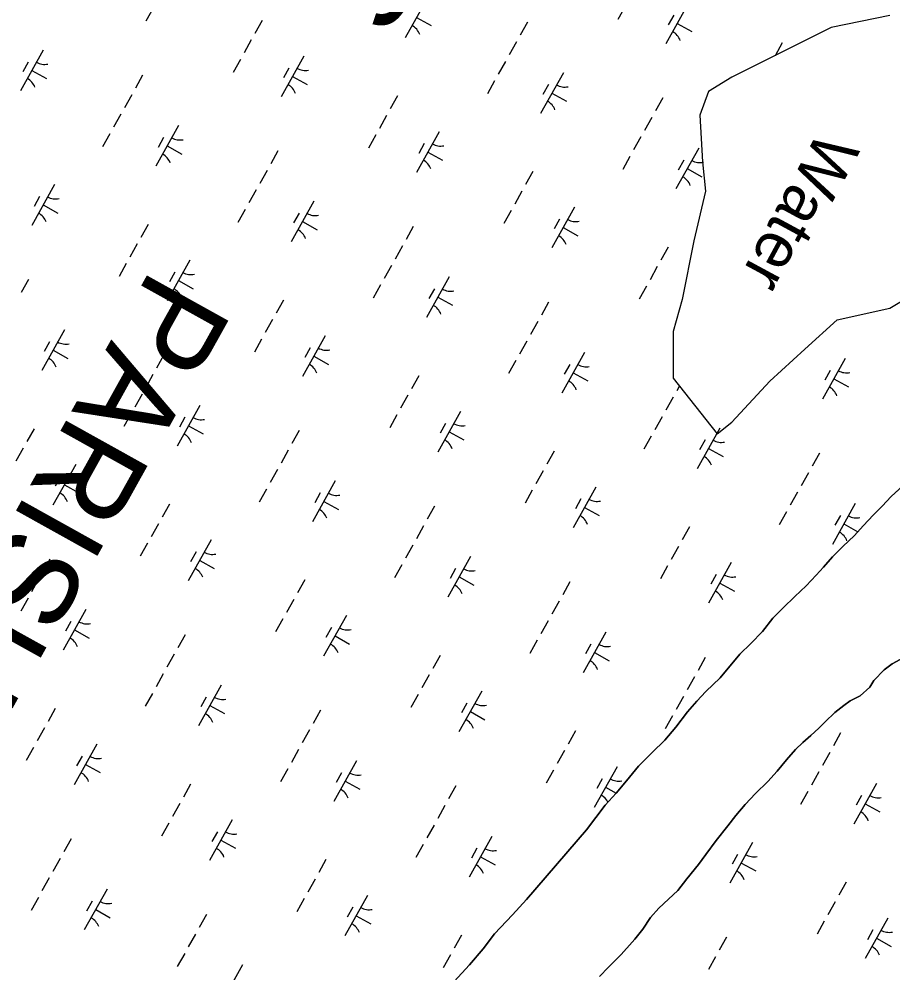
# Model space of a CAD drawing. Extents: x 3923531 to 3943530, y 207391 to 229799.
# Drawn here: x 3929310 to 3930247, y 215493 to 216516 of the extents above; entities that cross this region are included whole.
import ezdxf

# ---------------------------------------------------------------- set-up
doc = ezdxf.new("R2010")
doc.units = 0
for name, color, linetype in [('V-RIVR-IDEN', 7, 'Continuous'), ('V-TOPO-GNAM-IDEN', 7, 'Continuous'), ('V-TOPO-SHOR', 7, 'Continuous'), ('V-WETL-SWMP', 7, 'Continuous')]:
    doc.layers.add(name, color=color, linetype=linetype)

msp = doc.modelspace()

# ---------------------------------------------------------------- linework, layer by layer
at = {"layer": 'V-TOPO-SHOR'}
for points in [[(3930244, 216520.1), (3930181.2, 216507.5), (3930074.5, 216454.1), (3930049.4, 216438.5), (3930040, 216413.3), (3930043.1, 216363.1), (3930046.2, 216331.7), (3930033.7, 216278.4), (3930021.1, 216215.6), (3930011.7, 216181.1), (3930011.7, 216130.9), (3930058.8, 216071.2), (3930074.5, 216083.8), (3930115.3, 216127.7), (3930152.9, 216162.2), (3930187.5, 216193.6), (3930244, 216206.2), (3930275.4, 216225)], [(3929776.4, 215483.4), (3929793.1, 215501.4), (3929807.7, 215518.7), (3929819.9, 215534.8), (3929839.1, 215555.2), (3929854.3, 215571.6), (3929918.4, 215646.4), (3929938.7, 215672.7), (3929950.3, 215685.5), (3929961.5, 215699), (3929974.5, 215714.7), (3929989.1, 215729.4), (3930002.5, 215742.5), (3930014.3, 215756.6), (3930027, 215772.9), (3930036.8, 215784.3), (3930046.4, 215794.7), (3930062, 215809.6), (3930083.2, 215834.7), (3930095, 215846.4), (3930107.2, 215859.3), (3930118.4, 215873.3), (3930129.4, 215884.4), (3930142.2, 215896.6), (3930154.2, 215908.3), (3930165, 215919.5), (3930172.8, 215928.3), (3930182.6, 215939.3), (3930193.6, 215950.2), (3930206, 215962.2), (3930215.4, 215972.6), (3930226.4, 215984.3), (3930235.6, 215993.7), (3930245.4, 216004.1), (3930274.1, 216030.3)], [(3929932.5, 215489.1), (3929942.1, 215499.1), (3929955.7, 215512.4), (3929967.7, 215525.7), (3929970.3, 215528.9), (3929979, 215539.8), (3929987.2, 215552.2), (3929996.2, 215562.2), (3930006.6, 215572), (3930016.4, 215581.2), (3930026.2, 215593.6), (3930038.6, 215609.3), (3930046.5, 215619.7), (3930057.7, 215635), (3930070.3, 215650.7), (3930078.9, 215661.7), (3930088.8, 215673.4), (3930100, 215685.4), (3930113, 215698.1), (3930123.2, 215709.3), (3930133.2, 215721.6), (3930142.8, 215732.4), (3930150.8, 215740.2), (3930159.2, 215747.7), (3930167.9, 215755.3), (3930174.7, 215762.2), (3930184.9, 215772.1), (3930194.7, 215779.8), (3930201.3, 215784.6), (3930212.2, 215790.3), (3930222.4, 215799.3), (3930227, 215806.5), (3930237.8, 215817.9), (3930246.6, 215824.5), (3930255, 215829)]]:
    msp.add_lwpolyline(points, dxfattribs=at)
at = {"layer": 'V-WETL-SWMP'}
for p, q in [((3929470, 216557.8), (3929445.7, 216514.1)), ((3929748.5, 216540), (3929724.1, 216496.3)), ((3930028.1, 216533.5), (3930003.7, 216489.8)), ((3929960, 216529.9), (3929952.2, 216516)), ((3929570.6, 216515), (3929562.8, 216501)), ((3929736.3, 216518.1), (3929752, 216509.4)), ((3929855.1, 216512.9), (3929847.3, 216499)), ((3930012.1, 216520.7), (3930006.2, 216510.2)), ((3930015.9, 216511.7), (3930031.6, 216502.9)), ((3929558.9, 216494.1), (3929551.1, 216480.1)), ((3929843.4, 216492), (3929835.6, 216478)), ((3929335.6, 216483.1), (3929311.2, 216439.5)), ((3930128.6, 216490.7), (3930120.8, 216476.8)), ((3929547.2, 216473.1), (3929539.4, 216459.1)), ((3929615.3, 216476.7), (3929590.9, 216433)), ((3929831.7, 216471), (3929823.9, 216457.1)), ((3929319.6, 216470.3), (3929313.8, 216459.8)), ((3929323.4, 216461.3), (3929339.2, 216452.5)), ((3929599.3, 216463.8), (3929593.4, 216453.4)), ((3929442.3, 216456.1), (3929434.5, 216442.1)), ((3929603.1, 216454.8), (3929618.8, 216446)), ((3929893.7, 216458.8), (3929869.3, 216415.2)), ((3929820, 216450.1), (3929812.2, 216436.1)), ((3929877.7, 216446), (3929871.8, 216435.5)), ((3929430.6, 216435.1), (3929422.8, 216421.2)), ((3929715.8, 216433.9), (3929708, 216419.9)), ((3929881.5, 216437), (3929897.2, 216428.2)), ((3930000.3, 216431.8), (3929992.5, 216417.8)), ((3929418.9, 216414.2), (3929411.1, 216400.2)), ((3929704.1, 216412.9), (3929696.3, 216399)), ((3929988.6, 216410.9), (3929980.8, 216396.9)), ((3929480.8, 216402), (3929456.5, 216358.4)), ((3929407.2, 216393.2), (3929399.4, 216379.3)), ((3929464.8, 216389.2), (3929459, 216378.7)), ((3929692.4, 216392), (3929684.6, 216378)), ((3929760.5, 216395.5), (3929736.1, 216351.9)), ((3929976.9, 216389.9), (3929969.1, 216375.9)), ((3929468.7, 216380.2), (3929484.4, 216371.4)), ((3929744.5, 216382.7), (3929738.6, 216372.2)), ((3929587.5, 216375), (3929579.7, 216361)), ((3929748.3, 216373.7), (3929764, 216364.9)), ((3929965.2, 216369), (3929957.4, 216355)), ((3930038.9, 216377.7), (3930014.5, 216334.1)), ((3930022.9, 216364.9), (3930017, 216354.4)), ((3929575.8, 216354), (3929568, 216340.1)), ((3929861, 216352.8), (3929853.2, 216338.8)), ((3930026.7, 216355.9), (3930042.4, 216347.1)), ((3929347.6, 216338.7), (3929323.3, 216295)), ((3929564.1, 216333.1), (3929556.3, 216319.1)), ((3929849.3, 216331.8), (3929841.5, 216317.8)), ((3929331.6, 216325.9), (3929325.8, 216315.4)), ((3929626.1, 216320.9), (3929601.7, 216277.2)), ((3929335.5, 216316.9), (3929351.2, 216308.1)), ((3929552.4, 216312.1), (3929544.6, 216298.1)), ((3929610.1, 216308.1), (3929604.2, 216297.6)), ((3929837.6, 216310.9), (3929829.8, 216296.9)), ((3929905.7, 216314.4), (3929881.3, 216270.8)), ((3929613.9, 216299.1), (3929629.6, 216290.3)), ((3929889.7, 216301.6), (3929883.8, 216291.1)), ((3929448.2, 216295.9), (3929440.4, 216282)), ((3929732.7, 216293.8), (3929724.9, 216279.9)), ((3929893.5, 216292.6), (3929909.2, 216283.8)), ((3929436.5, 216275), (3929428.7, 216261)), ((3929721, 216272.9), (3929713.2, 216258.9)), ((3930006.2, 216271.6), (3929998.4, 216257.7)), ((3929492.9, 216257.6), (3929468.5, 216213.9)), ((3929424.8, 216254), (3929417, 216240.1)), ((3929709.3, 216251.9), (3929701.5, 216238)), ((3929994.5, 216250.7), (3929986.7, 216236.7)), ((3929319.9, 216237), (3929312.1, 216223)), ((3929476.9, 216244.7), (3929471, 216234.3)), ((3929480.7, 216235.7), (3929496.4, 216227)), ((3929771.3, 216239.8), (3929746.9, 216196.1)), ((3929697.6, 216231), (3929689.8, 216217)), ((3929755.3, 216226.9), (3929749.4, 216216.5)), ((3929982.8, 216229.7), (3929975, 216215.8)), ((3929759.1, 216217.9), (3929774.8, 216209.2)), ((3929593.4, 216214.8), (3929585.6, 216200.8)), ((3929877.9, 216212.7), (3929870.1, 216198.8)), ((3929581.7, 216193.9), (3929573.9, 216179.9)), ((3929866.2, 216191.8), (3929858.4, 216177.8)), ((3929358.5, 216182.9), (3929334.1, 216139.3)), ((3929638.1, 216176.4), (3929613.7, 216132.8)), ((3929342.5, 216170.1), (3929336.6, 216159.6)), ((3929570, 216172.9), (3929562.2, 216158.9)), ((3929854.5, 216170.8), (3929846.7, 216156.9)), ((3929346.3, 216161.1), (3929362, 216152.3)), ((3929465.1, 216155.9), (3929457.3, 216141.9)), ((3929622.1, 216163.6), (3929616.2, 216153.1)), ((3929625.9, 216154.6), (3929641.6, 216145.8)), ((3929916.5, 216158.6), (3929892.1, 216115)), ((3929842.8, 216149.9), (3929835, 216135.9)), ((3929900.5, 216145.8), (3929894.6, 216135.3)), ((3930196.1, 216152.2), (3930171.7, 216108.5)), ((3929453.4, 216134.9), (3929445.6, 216121)), ((3929738.6, 216133.7), (3929730.8, 216119.7)), ((3929904.3, 216136.8), (3929920, 216128)), ((3930180.1, 216139.3), (3930174.3, 216128.9)), ((3930183.9, 216130.3), (3930199.6, 216121.6)), ((3929441.7, 216114), (3929433.9, 216100)), ((3929726.9, 216112.7), (3929719.1, 216098.8)), ((3930018.2, 216122.7), (3930015.4, 216117.6)), ((3930011.4, 216110.6), (3930003.6, 216096.7)), ((3929430, 216093), (3929422.2, 216079.1)), ((3929503.7, 216101.8), (3929479.3, 216058.1)), ((3929783.3, 216095.3), (3929758.9, 216051.7)), ((3929487.7, 216089), (3929481.8, 216078.5)), ((3929715.2, 216091.8), (3929707.4, 216077.8)), ((3929767.3, 216082.5), (3929761.4, 216072)), ((3929999.7, 216089.7), (3929991.9, 216075.7)), ((3929325.8, 216076.8), (3929318, 216062.9)), ((3929491.5, 216080), (3929507.2, 216071.2)), ((3929610.3, 216074.8), (3929602.5, 216060.8)), ((3929771.1, 216073.5), (3929786.8, 216064.7)), ((3930061.7, 216077.5), (3930037.3, 216033.9)), ((3929988, 216068.7), (3929980.2, 216054.8)), ((3930045.7, 216064.7), (3930039.8, 216054.2)), ((3929314.1, 216055.9), (3929306.3, 216041.9)), ((3929598.6, 216053.8), (3929590.8, 216039.8)), ((3929883.8, 216052.6), (3929876, 216038.6)), ((3930049.5, 216055.7), (3930065.2, 216046.9)), ((3930168.4, 216050.5), (3930160.6, 216036.5)), ((3929370.5, 216038.5), (3929346.1, 215994.8)), ((3929586.9, 216032.9), (3929579.1, 216018.9)), ((3929872.1, 216031.6), (3929864.3, 216017.6)), ((3929354.5, 216025.7), (3929348.6, 216015.2)), ((3929648.9, 216020.7), (3929624.5, 215977)), ((3930156.7, 216029.5), (3930148.9, 216015.6)), ((3930274.1, 216030.3), (3930245.4, 216004.1)), ((3929358.3, 216016.7), (3929374, 216007.9)), ((3929575.2, 216011.9), (3929567.4, 215997.9)), ((3929860.4, 216010.7), (3929852.6, 215996.7)), ((3929928.5, 216014.2), (3929904.1, 215970.5)), ((3929632.9, 216007.8), (3929627, 215997.4)), ((3929912.5, 216001.4), (3929906.6, 215990.9)), ((3930145, 216008.6), (3930137.2, 215994.6)), ((3930245.4, 216004.1), (3930235.6, 215993.7)), ((3929471, 215995.7), (3929463.2, 215981.8)), ((3929636.7, 215998.8), (3929652.4, 215990.1)), ((3929755.5, 215993.6), (3929747.7, 215979.7)), ((3929916.3, 215992.4), (3929932, 215983.6)), ((3930206.9, 215996.4), (3930182.5, 215952.7)), ((3930235.6, 215993.7), (3930226.4, 215984.3)), ((3930133.3, 215987.6), (3930125.4, 215973.7)), ((3930190.9, 215983.6), (3930185.1, 215973.1)), ((3930226.4, 215984.3), (3930215.4, 215972.6)), ((3929459.3, 215974.8), (3929451.5, 215960.8)), ((3929743.8, 215972.7), (3929736, 215958.7)), ((3930029, 215971.4), (3930021.2, 215957.5)), ((3930194.7, 215974.6), (3930209.6, 215966.2)), ((3930215.4, 215972.6), (3930206, 215962.2)), ((3930206, 215962.2), (3930193.6, 215950.2)), ((3929447.6, 215953.8), (3929439.8, 215939.9)), ((3929515.7, 215957.4), (3929491.3, 215913.7)), ((3929732.1, 215951.7), (3929724.3, 215937.8)), ((3930017.3, 215950.5), (3930009.5, 215936.5)), ((3930193.6, 215950.2), (3930182.6, 215939.3)), ((3929499.7, 215944.5), (3929493.8, 215934.1)), ((3929794.1, 215939.5), (3929769.7, 215895.9)), ((3930182.6, 215939.3), (3930172.8, 215928.3)), ((3929342.7, 215936.8), (3929334.9, 215922.8)), ((3929503.5, 215935.5), (3929519.2, 215926.8)), ((3929720.4, 215930.8), (3929712.6, 215916.8)), ((3930005.6, 215929.5), (3929997.8, 215915.6)), ((3930073.7, 215933.1), (3930049.3, 215889.4)), ((3929778.1, 215926.7), (3929772.2, 215916.2)), ((3930057.7, 215920.2), (3930051.9, 215909.8)), ((3930165, 215919.5), (3930154.2, 215908.3)), ((3930172.8, 215928.3), (3930165, 215919.5)), ((3929331, 215915.9), (3929323.2, 215901.9)), ((3929616.2, 215914.6), (3929608.4, 215900.6)), ((3929781.9, 215917.7), (3929797.6, 215908.9)), ((3929900.8, 215912.5), (3929893, 215898.5)), ((3930061.5, 215911.2), (3930077.2, 215902.5)), ((3930154.2, 215908.3), (3930142.2, 215896.6)), ((3929319.3, 215894.9), (3929311.5, 215880.9)), ((3929604.5, 215893.6), (3929596.7, 215879.7)), ((3929889.1, 215891.6), (3929881.3, 215877.6)), ((3930142.2, 215896.6), (3930129.4, 215884.4)), ((3929381.3, 215882.7), (3929356.9, 215839.1)), ((3930129.4, 215884.4), (3930118.4, 215873.3)), ((3929365.3, 215869.9), (3929359.4, 215859.4)), ((3929592.8, 215872.7), (3929585, 215858.7)), ((3929660.9, 215876.2), (3929636.5, 215832.6)), ((3929877.4, 215870.6), (3929869.5, 215856.6)), ((3930118.4, 215873.3), (3930107.2, 215859.3)), ((3929369.1, 215860.9), (3929384.8, 215852.1)), ((3929644.9, 215863.4), (3929639, 215852.9)), ((3929939.3, 215858.4), (3929914.9, 215814.8)), ((3930107.2, 215859.3), (3930095, 215846.4)), ((3929487.9, 215855.7), (3929480.1, 215841.7)), ((3929648.7, 215854.4), (3929664.4, 215845.6)), ((3929865.6, 215849.7), (3929857.8, 215835.7)), ((3929923.3, 215845.6), (3929917.5, 215835.1)), ((3929927.1, 215836.6), (3929942.8, 215827.8)), ((3930095, 215846.4), (3930083.2, 215834.7)), ((3929476.2, 215834.7), (3929468.4, 215820.8)), ((3929761.4, 215833.5), (3929753.6, 215819.5)), ((3930046, 215831.4), (3930038.2, 215817.4)), ((3930083.2, 215834.7), (3930062, 215809.6)), ((3930255, 215829), (3930246.6, 215824.5)), ((3930237.8, 215817.9), (3930227, 215806.5)), ((3930246.6, 215824.5), (3930237.8, 215817.9)), ((3929464.5, 215813.8), (3929456.7, 215799.8)), ((3929749.7, 215812.5), (3929741.9, 215798.6)), ((3930034.3, 215810.4), (3930026.5, 215796.5)), ((3930062, 215809.6), (3930046.4, 215794.7)), ((3930227, 215806.5), (3930222.4, 215799.3)), ((3929526.5, 215801.6), (3929502.1, 215757.9)), ((3930222.4, 215799.3), (3930212.2, 215790.3)), ((3929452.8, 215792.8), (3929445, 215778.9)), ((3929510.5, 215788.8), (3929504.6, 215778.3)), ((3929738, 215791.6), (3929730.2, 215777.6)), ((3929806.1, 215795.1), (3929781.7, 215751.5)), ((3930022.6, 215789.5), (3930014.8, 215775.5)), ((3930046.4, 215794.7), (3930036.8, 215784.3)), ((3930212.2, 215790.3), (3930201.3, 215784.6)), ((3929348.6, 215776.6), (3929340.8, 215762.7)), ((3929514.3, 215779.8), (3929530, 215771)), ((3929790.1, 215782.3), (3929784.3, 215771.8)), ((3930036.8, 215784.3), (3930027, 215772.9)), ((3930194.7, 215779.8), (3930184.9, 215772.1)), ((3930201.3, 215784.6), (3930194.7, 215779.8)), ((3929633.2, 215774.6), (3929625.4, 215760.6)), ((3929793.9, 215773.3), (3929809.6, 215764.5)), ((3930010.9, 215768.5), (3930003.1, 215754.6)), ((3930027, 215772.9), (3930014.3, 215756.6)), ((3930184.9, 215772.1), (3930174.7, 215762.2)), ((3929336.9, 215755.7), (3929329.1, 215741.7)), ((3930014.3, 215756.6), (3930002.5, 215742.5)), ((3930167.9, 215755.3), (3930159.2, 215747.7)), ((3930174.7, 215762.2), (3930167.9, 215755.3)), ((3929621.5, 215753.6), (3929613.6, 215739.6)), ((3929906.6, 215752.4), (3929898.8, 215738.4)), ((3930159.2, 215747.7), (3930150.8, 215740.2)), ((3930191.2, 215750.3), (3930183.4, 215736.3)), ((3929325.2, 215734.7), (3929317.4, 215720.8)), ((3929393.3, 215738.3), (3929368.9, 215694.6)), ((3930002.5, 215742.5), (3929989.1, 215729.4)), ((3930150.8, 215740.2), (3930142.8, 215732.4)), ((3929377.3, 215725.4), (3929371.4, 215715)), ((3929609.7, 215732.7), (3929601.9, 215718.7)), ((3929894.9, 215731.4), (3929887.1, 215717.4)), ((3929989.1, 215729.4), (3929974.5, 215714.7)), ((3930142.8, 215732.4), (3930133.2, 215721.6)), ((3930179.5, 215729.3), (3930171.7, 215715.3)), ((3929381.1, 215716.4), (3929396.8, 215707.7)), ((3929671.7, 215720.5), (3929647.3, 215676.8)), ((3929951.3, 215714), (3929926.9, 215670.3)), ((3929974.5, 215714.7), (3929961.5, 215699)), ((3930133.2, 215721.6), (3930123.2, 215709.3)), ((3929598, 215711.7), (3929590.2, 215697.7)), ((3929655.7, 215707.6), (3929649.9, 215697.2)), ((3929883.2, 215710.4), (3929875.4, 215696.5)), ((3930123.2, 215709.3), (3930113, 215698.1)), ((3930167.8, 215708.4), (3930160, 215694.4)), ((3929493.8, 215695.5), (3929486, 215681.5)), ((3929659.5, 215698.6), (3929675.2, 215689.9)), ((3929778.4, 215693.4), (3929770.6, 215679.5)), ((3929935.3, 215701.2), (3929929.5, 215690.7)), ((3929961.5, 215699), (3929950.3, 215685.5)), ((3930113, 215698.1), (3930100, 215685.4)), ((3930229.7, 215696.2), (3930205.4, 215652.5)), ((3929950.3, 215685.5), (3929938.7, 215672.7)), ((3929939.1, 215692.2), (3929950.5, 215685.8)), ((3930100, 215685.4), (3930088.8, 215673.4)), ((3930156.1, 215687.4), (3930148.3, 215673.4)), ((3930213.7, 215683.3), (3930207.9, 215672.9)), ((3929482.1, 215674.6), (3929474.3, 215660.6)), ((3929766.7, 215672.5), (3929758.9, 215658.5)), ((3929938.7, 215672.7), (3929918.4, 215646.4)), ((3930088.8, 215673.4), (3930078.9, 215661.7)), ((3930217.5, 215674.3), (3930233.3, 215665.6)), ((3929470.4, 215653.6), (3929462.6, 215639.6)), ((3929538.5, 215657.1), (3929514.1, 215613.5)), ((3930078.9, 215661.7), (3930070.3, 215650.7)), ((3929522.5, 215644.3), (3929516.6, 215633.8)), ((3929755, 215651.5), (3929747.2, 215637.6)), ((3929918.4, 215646.4), (3929854.3, 215571.6)), ((3930070.3, 215650.7), (3930057.7, 215635)), ((3929365.5, 215636.6), (3929357.7, 215622.6)), ((3929526.3, 215635.3), (3929542, 215626.5)), ((3929816.9, 215639.3), (3929792.5, 215595.7)), ((3930057.7, 215635), (3930046.5, 215619.7)), ((3930096.5, 215632.9), (3930072.2, 215589.2)), ((3929743.3, 215630.6), (3929735.5, 215616.6)), ((3929800.9, 215626.5), (3929795.1, 215616)), ((3929353.8, 215615.6), (3929346, 215601.7)), ((3929639, 215614.4), (3929631.2, 215600.4)), ((3929804.7, 215617.5), (3929820.4, 215608.7)), ((3930046.5, 215619.7), (3930038.6, 215609.3)), ((3930080.5, 215620), (3930074.7, 215609.6)), ((3930038.6, 215609.3), (3930026.2, 215593.6)), ((3930084.3, 215611), (3930100.1, 215602.3)), ((3929342.1, 215594.7), (3929334.3, 215580.7)), ((3929627.3, 215593.4), (3929619.5, 215579.5)), ((3930026.2, 215593.6), (3930016.4, 215581.2)), ((3929404.1, 215582.5), (3929379.7, 215538.9)), ((3930016.4, 215581.2), (3930006.6, 215572)), ((3930197.1, 215590.1), (3930189.3, 215576.1)), ((3929330.4, 215573.7), (3929322.6, 215559.8)), ((3929615.6, 215572.5), (3929607.8, 215558.5)), ((3929683.7, 215576), (3929659.3, 215532.4)), ((3929854.3, 215571.6), (3929839.1, 215555.2)), ((3930006.6, 215572), (3929996.2, 215562.2)), ((3929388.1, 215569.7), (3929382.2, 215559.2)), ((3929391.9, 215560.7), (3929407.6, 215551.9)), ((3929667.7, 215563.2), (3929661.9, 215552.7)), ((3929996.2, 215562.2), (3929987.2, 215552.2)), ((3930185.4, 215569.2), (3930177.6, 215555.2)), ((3929510.8, 215555.5), (3929503, 215541.5)), ((3929671.5, 215554.2), (3929687.2, 215545.4)), ((3929839.1, 215555.2), (3929819.9, 215534.8)), ((3929987.2, 215552.2), (3929979, 215539.8)), ((3930241.8, 215551.7), (3930217.4, 215508.1)), ((3929979, 215539.8), (3929970.3, 215528.9)), ((3930173.7, 215548.2), (3930165.9, 215534.2)), ((3929499.1, 215534.5), (3929491.3, 215520.6)), ((3929784.3, 215533.3), (3929776.5, 215519.3)), ((3929819.9, 215534.8), (3929807.7, 215518.7)), ((3930068.8, 215531.2), (3930061, 215517.2)), ((3930225.7, 215538.9), (3930219.9, 215528.4)), ((3930229.6, 215529.9), (3930245.3, 215521.1)), ((3929967.7, 215525.7), (3929955.7, 215512.4)), ((3929970.3, 215528.9), (3929967.7, 215525.7)), ((3929487.4, 215513.6), (3929479.5, 215499.6)), ((3929772.5, 215512.3), (3929764.7, 215498.3)), ((3929807.7, 215518.7), (3929793.1, 215501.4)), ((3929955.7, 215512.4), (3929942.1, 215499.1)), ((3930057.1, 215510.2), (3930049.3, 215496.3)), ((3929549.3, 215501.4), (3929524.9, 215457.7)), ((3929793.1, 215501.4), (3929776.4, 215483.4)), ((3929942.1, 215499.1), (3929932.5, 215489.1))]:
    msp.add_line(p, q, dxfattribs=at)
for centre, start, end in [((3929723, 216493.9), 20.0381, 61.5817), ((3930002.6, 216487.4), 20.0381, 61.5817), ((3929337.1, 216485.3), 240.0381, 281.5817), ((3929616.7, 216478.8), 240.0381, 281.5817), ((3929310.2, 216437.1), 20.0381, 61.5817), ((3929589.8, 216430.6), 20.0381, 61.5817), ((3929895.2, 216461), 240.0381, 281.5817), ((3929868.2, 216412.8), 20.0381, 61.5817), ((3929482.3, 216404.2), 240.0381, 281.5817), ((3929762, 216397.7), 240.0381, 281.5817), ((3929455.4, 216355.9), 20.0381, 61.5817), ((3929735, 216349.5), 20.0381, 61.5817), ((3930040.4, 216379.9), 240.0381, 281.5817), ((3930013.4, 216331.7), 20.0381, 61.5817), ((3929349.1, 216340.9), 240.0381, 281.5817), ((3929322.2, 216292.6), 20.0381, 61.5817), ((3929627.5, 216323.1), 240.0381, 281.5817), ((3929907.2, 216316.6), 240.0381, 281.5817), ((3929600.6, 216274.8), 20.0381, 61.5817), ((3929880.2, 216268.3), 20.0381, 61.5817), ((3929494.3, 216259.7), 240.0381, 281.5817), ((3929467.4, 216211.5), 20.0381, 61.5817), ((3929772.8, 216241.9), 240.0381, 281.5817), ((3929745.8, 216193.7), 20.0381, 61.5817), ((3929359.9, 216185.1), 240.0381, 281.5817), ((3929639.6, 216178.6), 240.0381, 281.5817), ((3929333, 216136.9), 20.0381, 61.5817), ((3929612.6, 216130.4), 20.0381, 61.5817), ((3929918, 216160.8), 240.0381, 281.5817), ((3930197.6, 216154.3), 240.0381, 281.5817), ((3929891, 216112.6), 20.0381, 61.5817), ((3930170.7, 216106.1), 20.0381, 61.5817), ((3929505.2, 216104), 240.0381, 281.5817), ((3929784.8, 216097.5), 240.0381, 281.5817), ((3929478.2, 216055.7), 20.0381, 61.5817), ((3929757.8, 216049.3), 20.0381, 61.5817), ((3930063.2, 216079.7), 240.0381, 281.5817), ((3930036.2, 216031.5), 20.0381, 61.5817), ((3929372, 216040.7), 240.0381, 281.5817), ((3929345, 215992.4), 20.0381, 61.5817), ((3929650.4, 216022.8), 240.0381, 281.5817), ((3929930, 216016.4), 240.0381, 281.5817), ((3929623.4, 215974.6), 20.0381, 61.5817), ((3929903, 215968.1), 20.0381, 61.5817), ((3930208.4, 215998.6), 240.0381, 281.5817), ((3930181.5, 215950.3), 20.0381, 61.5817), ((3929517.2, 215959.5), 240.0381, 281.5817), ((3929490.2, 215911.3), 20.0381, 61.5817), ((3929795.6, 215941.7), 240.0381, 281.5817), ((3930075.2, 215935.2), 240.0381, 281.5817), ((3929768.6, 215893.5), 20.0381, 61.5817), ((3930048.3, 215887), 20.0381, 61.5817), ((3929382.8, 215884.9), 240.0381, 281.5817), ((3929662.4, 215878.4), 240.0381, 281.5817), ((3929355.8, 215836.7), 20.0381, 61.5817), ((3929635.4, 215830.2), 20.0381, 61.5817), ((3929940.8, 215860.6), 240.0381, 281.5817), ((3929913.9, 215812.4), 20.0381, 61.5817), ((3929528, 215803.8), 240.0381, 281.5817), ((3929807.6, 215797.3), 240.0381, 281.5817), ((3929501, 215755.5), 20.0381, 61.5817), ((3929780.7, 215749.1), 20.0381, 61.5817), ((3929394.8, 215740.4), 240.0381, 281.5817), ((3929367.8, 215692.2), 20.0381, 61.5817), ((3929673.2, 215722.6), 240.0381, 281.5817), ((3929952.8, 215716.2), 240.0381, 281.5817), ((3929646.2, 215674.4), 20.0381, 61.5817), ((3929925.9, 215667.9), 26.9489, 61.5817), ((3930231.2, 215698.3), 240.0381, 281.5817), ((3930204.3, 215650.1), 20.0381, 61.5817), ((3929540, 215659.3), 240.0381, 281.5817), ((3929513, 215611.1), 20.0381, 61.5817), ((3929818.4, 215641.5), 240.0381, 281.5817), ((3930098, 215635), 240.0381, 281.5817), ((3929791.5, 215593.3), 20.0381, 61.5817), ((3930071.1, 215586.8), 20.0381, 61.5817), ((3929405.6, 215584.7), 240.0381, 281.5817), ((3929685.2, 215578.2), 240.0381, 281.5817), ((3929378.6, 215536.4), 20.0381, 61.5817), ((3929658.3, 215530), 20.0381, 61.5817), ((3930243.2, 215553.9), 240.0381, 281.5817), ((3930216.3, 215505.7), 20.0381, 61.5817)]:
    msp.add_arc(centre, 17.6, start, end, dxfattribs=at)

# ---------------------------------------------------------------- texts
at = {"layer": 'V-RIVR-IDEN'}
msp.add_text('Water', height=50, rotation=241.5894, dxfattribs=at).set_placement((3930168.4, 216398.7))
at = {"layer": 'V-TOPO-GNAM-IDEN'}
for s, rotation, p in [('PLAQUEMINES', 240.8015, (3930087.5, 217385.2)), ('PARISH,', 240.9015, (3929452.2, 216250.9))]:
    msp.add_text(s, height=100, rotation=rotation, dxfattribs=at).set_placement(p)

doc.saveas('drawing.dxf')
